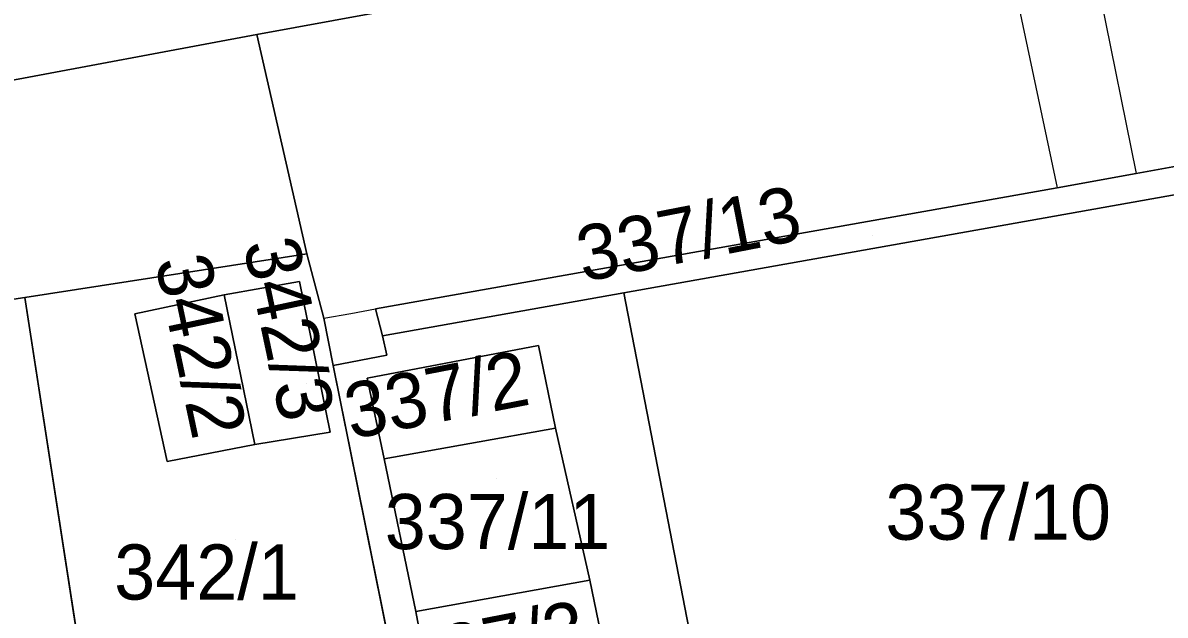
# Model space of a CAD drawing. Extents: x -263423 to -261326, y -1240067 to -1237864.
# Drawn here: x -263186.66 to -263145.25, y -1239364.08 to -1239342.6 of the extents above; entities that cross this region are included whole.
import ezdxf

# ---------------------------------------------------------------- set-up
doc = ezdxf.new("R2010")
doc.units = 0
for name, color, linetype in [('body_kn', 7, 'Continuous'), ('kladpar_druhypozemkov', 7, 'Continuous'), ('kladpar_hranice', 7, 'Continuous'), ('kladpar_parcelnecisla', 7, 'Continuous'), ('kladpar_plochy', 7, 'Continuous'), ('zappar_hrandruhpozemk', 7, 'Continuous')]:
    doc.layers.add(name, color=color, linetype=linetype)

msp = doc.modelspace()

# ---------------------------------------------------------------- linework, layer by layer
at = {"layer": 'body_kn'}
for p, q in [((-263178.18, -1239343.03), (-263178.18, -1239343.03)), ((-263178.18, -1239343.03), (-263178.18, -1239343.03)), ((-263146.3, -1239348.07), (-263146.3, -1239348.07)), ((-263149.16, -1239348.59), (-263149.16, -1239348.59)), ((-263176.36, -1239350.98), (-263176.36, -1239350.98)), ((-263176.63, -1239351.98), (-263176.63, -1239351.98)), ((-263176.63, -1239351.98), (-263176.63, -1239351.98)), ((-263179.36, -1239352.47), (-263179.36, -1239352.47)), ((-263179.36, -1239352.47), (-263179.36, -1239352.47)), ((-263164.87, -1239352.4), (-263164.87, -1239352.4)), ((-263164.87, -1239352.4), (-263164.87, -1239352.4)), ((-263186.59, -1239352.57), (-263186.59, -1239352.57)), ((-263182.6, -1239353.16), (-263182.6, -1239353.16)), ((-263175.75, -1239353.32), (-263175.75, -1239353.32)), ((-263175.75, -1239353.32), (-263175.75, -1239353.32)), ((-263174.77, -1239353.14), (-263174.77, -1239353.14)), ((-263173.88, -1239352.98), (-263173.88, -1239352.98)), ((-263173.62, -1239353.96), (-263173.62, -1239353.96)), ((-263167.96, -1239354.31), (-263167.96, -1239354.31)), ((-263167.96, -1239354.31), (-263167.96, -1239354.31)), ((-263173.47, -1239354.66), (-263173.47, -1239354.66)), ((-263175.41, -1239355.03), (-263175.41, -1239355.03)), ((-263174.18, -1239355.49), (-263174.18, -1239355.49)), ((-263175.52, -1239357.45), (-263175.52, -1239357.45)), ((-263167.35, -1239357.3), (-263167.35, -1239357.3)), ((-263178.25, -1239357.89), (-263178.25, -1239357.89)), ((-263181.43, -1239358.51), (-263181.43, -1239358.51)), ((-263173.56, -1239358.42), (-263173.56, -1239358.42)), ((-263166.1, -1239362.82), (-263166.1, -1239362.82)), ((-263166.1, -1239362.82), (-263166.1, -1239362.82)), ((-263172.41, -1239363.95), (-263172.41, -1239363.95)), ((-263172.41, -1239363.95), (-263172.41, -1239363.95))]:
    msp.add_line(p, q, dxfattribs=at)
at = {"layer": 'kladpar_druhypozemkov'}
for p, q in [((-263155.86, -1239350.31), (-263155.86, -1239350.31)), ((-263169.76, -1239355.29), (-263169.76, -1239355.29)), ((-263176.36, -1239355.69), (-263176.36, -1239355.69)), ((-263179.46, -1239356.29), (-263179.46, -1239356.29)), ((-263169.48, -1239359.14), (-263169.48, -1239359.14)), ((-263150.99, -1239359.43), (-263150.99, -1239359.43)), ((-263178.94, -1239361.34), (-263178.94, -1239361.34)), ((-263168.99, -1239364.08), (-263168.99, -1239364.08))]:
    msp.add_line(p, q, dxfattribs=at)
at = {"layer": 'kladpar_hranice'}
for points in [[(-263151.37, -1239338.12), (-263178.18, -1239343.03), (-263206.86, -1239348.4), (-263208, -1239349.41), (-263208.9, -1239350.81), (-263209.41, -1239352.21), (-263209.74, -1239353.73), (-263209.87, -1239355.13), (-263209.69, -1239356.08), (-263209.39, -1239359.46), (-263211.48, -1239359.64), (-263211.85, -1239356.46), (-263212.69, -1239349.58), (-263212.99, -1239346.46), (-263213.95, -1239336.28)], [(-263168.81, -1239382.41), (-263169.02, -1239381.42), (-263166.55, -1239380.94), (-263166.79, -1239379.71), (-263164.66, -1239379.28), (-263164.43, -1239380.52), (-263164.26, -1239381.51), (-263140.92, -1239376.91), (-263141.43, -1239358.96), (-263141.5, -1239356.2), (-263141.78, -1239347.25), (-263146.3, -1239348.07), (-263149.16, -1239348.59), (-263173.88, -1239352.98), (-263173.62, -1239353.96), (-263173.47, -1239354.66), (-263175.41, -1239355.03), (-263175.75, -1239353.32), (-263176.36, -1239350.98), (-263178.18, -1239343.03), (-263151.37, -1239338.12)], [(-263178.18, -1239343.03), (-263176.36, -1239350.98), (-263186.59, -1239352.57), (-263196.36, -1239354.05), (-263196.42, -1239353.6), (-263199.79, -1239354.1), (-263199.73, -1239354.54), (-263209.69, -1239356.08), (-263209.87, -1239355.13), (-263209.74, -1239353.73), (-263209.41, -1239352.21), (-263208.9, -1239350.81), (-263208, -1239349.41), (-263206.86, -1239348.4), (-263178.18, -1239343.03)], [(-263164.43, -1239380.52), (-263159.6, -1239379.58), (-263141.98, -1239376.13), (-263142.88, -1239348.48), (-263164.87, -1239352.4), (-263173.62, -1239353.96), (-263173.88, -1239352.98), (-263149.16, -1239348.59), (-263146.3, -1239348.07), (-263141.78, -1239347.25), (-263141.5, -1239356.2), (-263141.43, -1239358.96), (-263140.92, -1239376.91), (-263164.26, -1239381.51), (-263164.43, -1239380.52)], [(-263141.98, -1239376.13), (-263159.6, -1239379.58), (-263164.87, -1239352.4), (-263142.88, -1239348.48), (-263141.98, -1239376.13)], [(-263186.59, -1239352.57), (-263176.36, -1239350.98), (-263175.75, -1239353.32)], [(-263178.25, -1239357.89), (-263175.52, -1239357.45), (-263176.63, -1239351.98), (-263179.36, -1239352.47), (-263182.6, -1239353.16), (-263181.43, -1239358.51), (-263178.25, -1239357.89)], [(-263176.63, -1239351.98), (-263175.52, -1239357.45), (-263178.25, -1239357.89), (-263179.36, -1239352.47), (-263176.63, -1239351.98)], [(-263179.36, -1239352.47), (-263178.25, -1239357.89), (-263181.43, -1239358.51), (-263182.6, -1239353.16), (-263179.36, -1239352.47)], [(-263173.33, -1239365.34), (-263175.41, -1239355.03), (-263173.47, -1239354.66), (-263173.62, -1239353.96), (-263164.87, -1239352.4)], [(-263164.87, -1239352.4), (-263159.6, -1239379.58)], [(-263199.73, -1239354.54), (-263199.79, -1239354.1), (-263196.42, -1239353.6), (-263196.36, -1239354.05), (-263186.59, -1239352.57), (-263184.51, -1239366), (-263185.34, -1239366.12), (-263190.41, -1239366.92), (-263194.35, -1239367.48), (-263197.01, -1239367.78), (-263197.45, -1239367.91), (-263194.37, -1239394.06), (-263195.63, -1239394.31), (-263207.75, -1239396.1), (-263210.4, -1239369.95), (-263211.48, -1239359.64), (-263209.39, -1239359.46), (-263209.69, -1239356.08), (-263199.73, -1239354.54)], [(-263175.75, -1239353.32), (-263175.41, -1239355.03), (-263173.33, -1239365.34), (-263176.55, -1239365.84), (-263179.76, -1239366.33), (-263178.52, -1239372.2), (-263177.42, -1239378.31), (-263174.24, -1239377.75), (-263170.94, -1239377.06), (-263170.02, -1239381.46), (-263169.78, -1239382.6), (-263169.65, -1239383.24), (-263172.69, -1239383.8), (-263175.42, -1239384.36), (-263178.4, -1239384.92), (-263181.77, -1239385.54), (-263185.34, -1239366.12), (-263184.51, -1239366), (-263186.59, -1239352.57)], [(-263167.96, -1239354.31), (-263167.35, -1239357.3), (-263173.56, -1239358.42), (-263174.18, -1239355.49), (-263167.96, -1239354.31)], [(-263165.48, -1239365.86), (-263166.1, -1239362.82), (-263167.35, -1239357.3), (-263167.96, -1239354.31), (-263174.18, -1239355.49), (-263173.56, -1239358.42), (-263172.41, -1239363.95), (-263171.84, -1239366.99)], [(-263172.41, -1239363.95), (-263173.56, -1239358.42), (-263167.35, -1239357.3), (-263166.1, -1239362.82), (-263172.41, -1239363.95)], [(-263166.1, -1239362.82), (-263165.48, -1239365.86), (-263171.84, -1239366.99), (-263172.41, -1239363.95), (-263166.1, -1239362.82)]]:
    msp.add_lwpolyline(points, dxfattribs=at)
at = {"layer": 'kladpar_plochy'}
for p, q in [((-263186.59, -1239352.57), (-263176.36, -1239350.98)), ((-263176.36, -1239350.98), (-263175.75, -1239353.32)), ((-263176.63, -1239351.98), (-263179.36, -1239352.47)), ((-263175.52, -1239357.45), (-263176.63, -1239351.98)), ((-263179.36, -1239352.47), (-263182.6, -1239353.16)), ((-263184.51, -1239366), (-263186.59, -1239352.57)), ((-263182.6, -1239353.16), (-263181.43, -1239358.51)), ((-263175.75, -1239353.32), (-263175.41, -1239355.03)), ((-263175.41, -1239355.03), (-263173.33, -1239365.34)), ((-263178.25, -1239357.89), (-263175.52, -1239357.45)), ((-263181.43, -1239358.51), (-263178.25, -1239357.89))]:
    msp.add_line(p, q, dxfattribs=at)
for points in [[(-263151.37, -1239338.12), (-263178.18, -1239343.03), (-263206.86, -1239348.4), (-263208, -1239349.41), (-263208.9, -1239350.81), (-263209.41, -1239352.21), (-263209.74, -1239353.73), (-263209.87, -1239355.13), (-263209.69, -1239356.08), (-263209.39, -1239359.46), (-263211.48, -1239359.64), (-263211.85, -1239356.46), (-263212.69, -1239349.58), (-263212.99, -1239346.46), (-263213.95, -1239336.28)], [(-263141.78, -1239347.25), (-263146.3, -1239348.07), (-263149.16, -1239348.59), (-263173.88, -1239352.98), (-263173.62, -1239353.96), (-263173.47, -1239354.66), (-263175.41, -1239355.03), (-263175.75, -1239353.32), (-263176.36, -1239350.98), (-263178.18, -1239343.03), (-263151.37, -1239338.12)], [(-263173.33, -1239365.34), (-263175.41, -1239355.03), (-263173.47, -1239354.66), (-263173.62, -1239353.96), (-263164.87, -1239352.4), (-263159.6, -1239379.58)], [(-263165.48, -1239365.86), (-263166.1, -1239362.82), (-263167.35, -1239357.3), (-263167.96, -1239354.31), (-263174.18, -1239355.49), (-263173.56, -1239358.42), (-263172.41, -1239363.95), (-263171.84, -1239366.99)]]:
    msp.add_lwpolyline(points, dxfattribs=at)
for points in [[(-263178.18, -1239343.03), (-263176.36, -1239350.98), (-263186.59, -1239352.57), (-263196.36, -1239354.05), (-263196.42, -1239353.6), (-263199.79, -1239354.1), (-263199.73, -1239354.54), (-263209.69, -1239356.08), (-263209.87, -1239355.13), (-263209.74, -1239353.73), (-263209.41, -1239352.21), (-263208.9, -1239350.81), (-263208, -1239349.41), (-263206.86, -1239348.4)], [(-263164.43, -1239380.52), (-263159.6, -1239379.58), (-263141.98, -1239376.13), (-263142.88, -1239348.48), (-263164.87, -1239352.4), (-263173.62, -1239353.96), (-263173.88, -1239352.98), (-263149.16, -1239348.59), (-263146.3, -1239348.07), (-263141.78, -1239347.25), (-263141.5, -1239356.2), (-263141.43, -1239358.96), (-263140.92, -1239376.91), (-263164.26, -1239381.51)], [(-263141.98, -1239376.13), (-263159.6, -1239379.58), (-263164.87, -1239352.4), (-263142.88, -1239348.48)], [(-263176.63, -1239351.98), (-263175.52, -1239357.45), (-263178.25, -1239357.89), (-263179.36, -1239352.47)], [(-263179.36, -1239352.47), (-263178.25, -1239357.89), (-263181.43, -1239358.51), (-263182.6, -1239353.16)], [(-263199.73, -1239354.54), (-263199.79, -1239354.1), (-263196.42, -1239353.6), (-263196.36, -1239354.05), (-263186.59, -1239352.57), (-263184.51, -1239366), (-263185.34, -1239366.12), (-263190.41, -1239366.92), (-263194.35, -1239367.48), (-263197.01, -1239367.78), (-263197.45, -1239367.91), (-263194.37, -1239394.06), (-263195.63, -1239394.31), (-263207.75, -1239396.1), (-263210.4, -1239369.95), (-263211.48, -1239359.64), (-263209.39, -1239359.46), (-263209.69, -1239356.08)], [(-263167.96, -1239354.31), (-263167.35, -1239357.3), (-263173.56, -1239358.42), (-263174.18, -1239355.49)], [(-263172.41, -1239363.95), (-263173.56, -1239358.42), (-263167.35, -1239357.3), (-263166.1, -1239362.82)], [(-263166.1, -1239362.82), (-263165.48, -1239365.86), (-263171.84, -1239366.99), (-263172.41, -1239363.95)]]:
    msp.add_lwpolyline(points, close=True, dxfattribs=at)
at = {"layer": 'zappar_hrandruhpozemk'}
for p, q in [((-263148.42, -1239337.56), (-263146.3, -1239348.07)), ((-263151.37, -1239338.12), (-263149.16, -1239348.59))]:
    msp.add_line(p, q, dxfattribs=at)
msp.add_lwpolyline([(-263175.75, -1239353.32), (-263174.77, -1239353.14), (-263173.88, -1239352.98)], dxfattribs=at)

# ---------------------------------------------------------------- texts
at = {"layer": 'kladpar_parcelnecisla'}
for s, rotation, p in [('337/13', 11, (-263166.353, -1239352.009)), ('342/3', 282, (-263178.678, -1239350.622)), ('342/2', 282, (-263181.875, -1239351.238)), ('337/2', 11, (-263174.764, -1239357.709)), ('337/3', 11, (-263172.689, -1239366.762))]:
    msp.add_text(s, height=2, rotation=rotation, dxfattribs=at).set_placement(p)
for s, p in [('337/10', (-263155.39, -1239361.35)), ('337/11', (-263173.539, -1239361.69)), ('342/1', (-263183.349, -1239363.52))]:
    msp.add_text(s, height=2, dxfattribs=at).set_placement(p)

doc.saveas('drawing.dxf')
